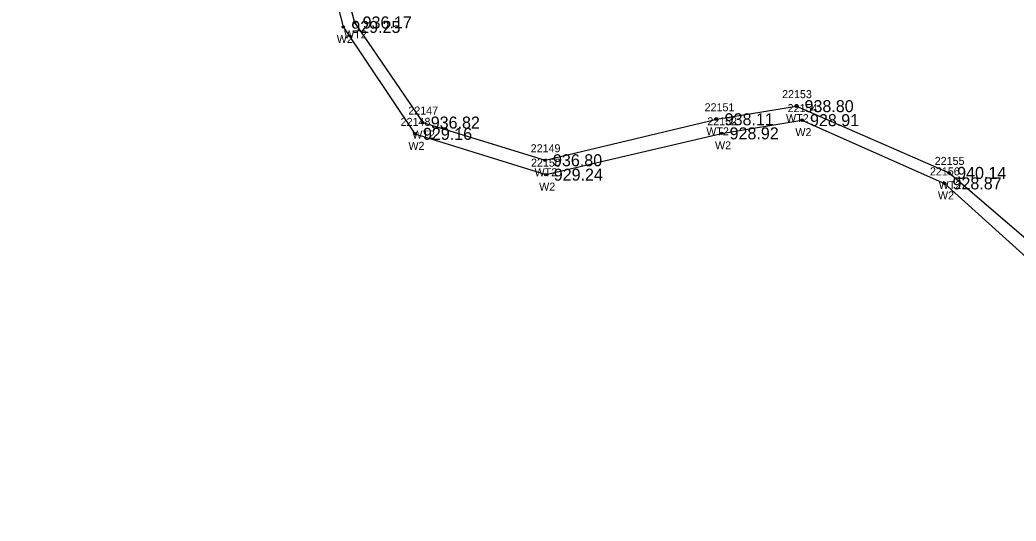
# Model space of a CAD drawing. Extents: x 1576181 to 1577685, y 1099396 to 1101490.
# Drawn here: x 1577444.3 to 1577568.7, y 1100754.8 to 1100817.4 of the extents above; entities that cross this region are included whole.
import ezdxf

# ---------------------------------------------------------------- set-up
doc = ezdxf.new("R2010")
doc.units = 0
for name, color, linetype in [('RD_DTM_BkLn2', 7, 'Continuous'), ('RD_EX_BldgApp', 7, 'Continuous'), ('RD_EX_Misc_txCode', 7, 'Continuous'), ('RD_EX_TX_Misc_ELEV', 7, 'Continuous'), ('RD_SMD_Locator', 7, 'Continuous')]:
    doc.layers.add(name, color=color, linetype=linetype)

msp = doc.modelspace()

# ---------------------------------------------------------------- linework, layer by layer
at = {"layer": 'RD_DTM_BkLn2'}
msp.add_lwpolyline([(1577432.53, 1100853.96), (1577434.36, 1100852.19), (1577447.88, 1100856.09), (1577457.13, 1100856.82), (1577470.14, 1100851.87), (1577480.17, 1100839.59), (1577486.13, 1100817.13), (1577494.64, 1100804.62), (1577509.91, 1100799.91), (1577531.35, 1100805.03), (1577541.32, 1100806.67), (1577560.38, 1100798.33), (1577576.37, 1100784.65), (1577583.76, 1100755.46)], dxfattribs=at)
at = {"layer": 'RD_EX_BldgApp'}
msp.add_lwpolyline([(1577431.47, 1100853.57), (1577434.21, 1100851.02), (1577448.25, 1100855.22), (1577457, 1100855.58), (1577470.32, 1100850.24), (1577479.05, 1100838.66), (1577484.72, 1100816.57), (1577493.67, 1100803.21), (1577510, 1100798.11), (1577531.96, 1100803.27), (1577542, 1100804.92), (1577559.8, 1100797.02), (1577574.7, 1100783.55), (1577581.82, 1100754.82)], dxfattribs=at)
at = {"layer": 'RD_SMD_Locator'}
for centre in [(1577484.72, 1100816.57), (1577486.13, 1100817.13), (1577541.32, 1100806.67), (1577531.35, 1100805.03), (1577542, 1100804.92), (1577494.64, 1100804.62), (1577493.67, 1100803.21), (1577531.96, 1100803.27), (1577509.91, 1100799.91), (1577510, 1100798.11), (1577560.38, 1100798.33), (1577559.8, 1100797.02)]:
    msp.add_circle(centre, 0.15, dxfattribs=at)

# ---------------------------------------------------------------- texts
at = {"layer": 'RD_EX_Misc_txCode'}
for s, p in [('WT2', (1577484.82, 1100815.13)), ('W2', (1577483.9, 1100814.57)), ('22153', (1577539.52, 1100807.67)), ('22147', (1577492.84, 1100805.62)), ('22151', (1577529.84, 1100806.03)), ('22154', (1577540.21, 1100805.92)), ('22148', (1577491.88, 1100804.21)), ('22152', (1577530.17, 1100804.27)), ('WT2', (1577540.01, 1100804.67)), ('WT2', (1577530.05, 1100803.03)), ('W2', (1577541.18, 1100802.92)), ('WT2', (1577493.33, 1100802.62)), ('W2', (1577492.85, 1100801.21)), ('22149', (1577508.12, 1100800.91)), ('W2', (1577531.14, 1100801.27)), ('22150', (1577508.16, 1100799.11)), ('22155', (1577558.58, 1100799.33)), ('WT2', (1577508.61, 1100797.91)), ('22156', (1577557.98, 1100798.02)), ('W2', (1577509.18, 1100796.11)), ('WT2', (1577559.07, 1100796.33)), ('W2', (1577558.98, 1100795.02))]:
    msp.add_text(s, height=1, dxfattribs=at).set_placement(p)
at = {"layer": 'RD_EX_TX_Misc_ELEV'}
for s, p in [('929.25', (1577485.72, 1100815.82)), ('936.17', (1577487.13, 1100816.38)), ('938.80', (1577542.32, 1100805.92)), ('936.82', (1577495.64, 1100803.87)), ('938.11', (1577532.35, 1100804.28)), ('928.91', (1577543, 1100804.17)), ('929.16', (1577494.67, 1100802.46)), ('928.92', (1577532.96, 1100802.52)), ('936.80', (1577510.91, 1100799.16)), ('929.24', (1577511, 1100797.36)), ('940.14', (1577561.38, 1100797.58)), ('928.87', (1577560.8, 1100796.27))]:
    msp.add_text(s, height=1.5, dxfattribs=at).set_placement(p)

doc.saveas('drawing.dxf')
